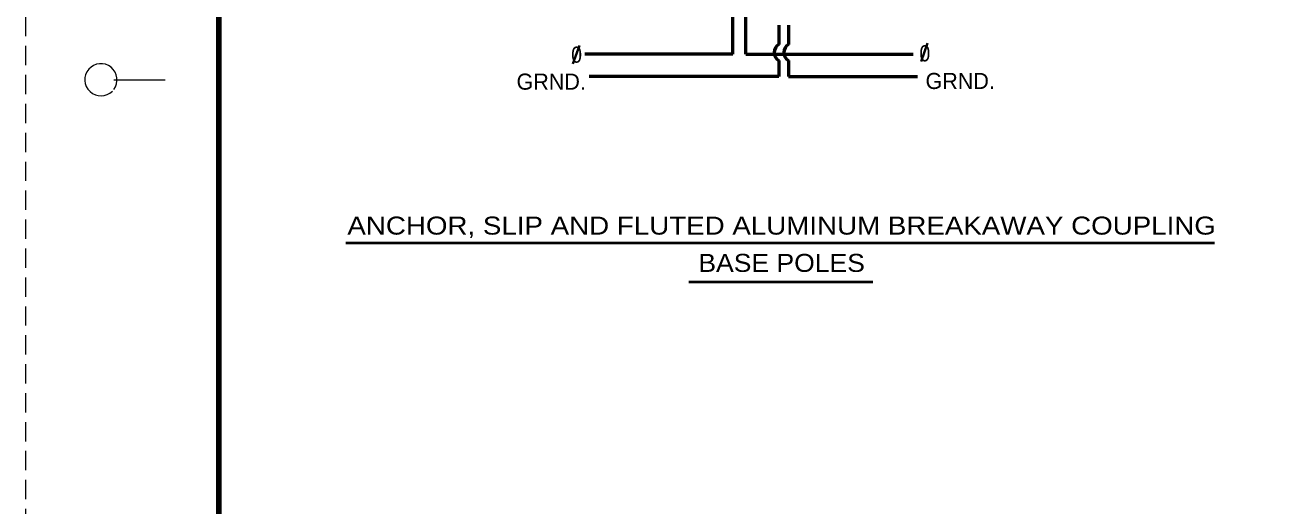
# Model space of a CAD drawing. Extents: x -153 to 527, y -247 to 194.
# Drawn here: x -153.1 to 43, y -26.5 to 48.2 of the extents above; entities that cross this region are included whole.
import ezdxf
from ezdxf.enums import TextEntityAlignment as Align

# ---------------------------------------------------------------- set-up
doc = ezdxf.new("R2010")
doc.units = 0
doc.linetypes.add('MEDIUM_DASHED', pattern=[4.5, 3, -1.5])
doc.layers.add('1', color=7, linetype='Continuous', lineweight=53)
doc.layers.add('61', color=7, linetype='Continuous', lineweight=35)

msp = doc.modelspace()

# ---------------------------------------------------------------- linework, layer by layer
at = {"layer": '1', "linetype": 'MEDIUM_DASHED', "lineweight": 13}
msp.add_line((-153.062, 193.509), (-153.122, -246.531), dxfattribs=at)
at = {"layer": '1'}
for p, q in [((-43.172, 43.732), (-43.172, 90.47)), ((-41.172, 43.732), (-41.172, 90.47)), ((-36.012, 48.231), (-36.012, 45.231)), ((-34.512, 48.231), (-34.512, 45.231)), ((-43.172, 43.732), (-66.171, 43.732)), ((-41.172, 43.732), (-15.171, 43.732)), ((-36.012, 42.731), (-36.012, 40.231)), ((-34.512, 42.731), (-34.512, 40.231)), ((-36.012, 40.231), (-65.512, 40.231)), ((-34.512, 40.231), (-14.512, 40.231))]:
    msp.add_line(p, q, dxfattribs=at)
at = {"layer": '1', "lineweight": 35}
for p, q in [((-12.912, 45.419), (-13.943, 42.586)), ((-66.993, 45.054), (-68.025, 42.221))]:
    msp.add_line(p, q, dxfattribs=at)
at = {"layer": '1', "lineweight": 40}
for p, q in [((-103.326, 14.41), (31.635, 14.41)), ((-50.026, 8.298), (-21.419, 8.298))]:
    msp.add_line(p, q, dxfattribs=at)
at = {"layer": '1'}
for centre in [(-35.375, 43.981), (-33.875, 43.981)]:
    msp.add_arc(centre, 1.403, 116.97883, 243.02117, dxfattribs=at)
at = {"layer": '61', "lineweight": 13}
msp.add_line((-139.362, 39.749), (-131.362, 39.749), dxfattribs=at)
at = {"layer": '61', "lineweight": 158}
msp.add_lwpolyline([(515.978, 183.509), (-123.062, 183.509), (-123.062, -236.511)], dxfattribs=at)
at = {"layer": '61', "lineweight": 13}
msp.add_arc((-141.364, 39.75), 2.5, 323.13009, 315.37577, dxfattribs=at)

# ---------------------------------------------------------------- texts
at = {"layer": '1', "width": 0.9}
for p in [(-14.187, 42.611), (-68.294, 42.402)]:
    msp.add_text('0', height=2.5, dxfattribs=at).set_placement(p)
at = {"layer": '1'}
for p in [(-76.788, 38.207), (-13.244, 38.312)]:
    msp.add_text('GRND.', height=2.5, dxfattribs=at).set_placement(p)
for s, width, p in [('ANCHOR, SLIP AND FLUTED ALUMINUM BREAKAWAY COUPLING', 1.15, (-35.601, 15.666)), ('BASE POLES', 1.1, (-35.601, 9.866))]:
    msp.add_text(s, height=2.8, dxfattribs=dict(at, width=width)).set_placement(p, align=Align.CENTER)

doc.saveas('drawing.dxf')
